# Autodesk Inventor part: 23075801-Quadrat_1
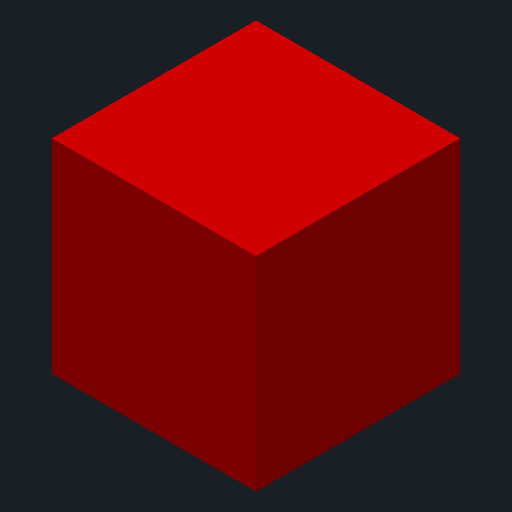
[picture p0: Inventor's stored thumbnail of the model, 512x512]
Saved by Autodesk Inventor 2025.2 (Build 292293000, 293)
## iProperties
Company: Ed. Züblin AG
RuleStatus: InUse
Created: 2025-03
Part Number: 23075801-Quadrat_1
Material: Stahlbeton C30/37
Document SubType Name: Modeling
Designer: FrodlSte
Mass: 2.5e+06 g
Surface Area: 60000 cm^2
Volume: 1e+06 cm^3
Density: 2.5 g/cm^3
Appearance: Beton C30/37
Description: Ausbruch
z_Bereich: Tunnelbau
z_Direktion: Tief- und Tunnelbau
z_Konzerneinheit: Zentrale Technik
z_Matchkey: =<z_Matchkey_010>_<z_Matchkey_020>_<z_Matchkey_030>_<z_Matchkey_040>_<z_Matchkey_050>_<z_Matchkey_060>_<z_Matchkey_070>_<z_Matchkey_080>_<z_Matchkey_090>_<z_Mat
cpiComponentType: Attribut
cpiFitMatchkey: =<z_Matchkey>
z_Matchkey_010: xxxxx
z_Matchkey_020: 5DTUB
z_Matchkey_030: xxx
z_Matchkey_040: xxx
z_Matchkey_050: xxx
z_Matchkey_060: xxx
z_Matchkey_070: xxx
z_Matchkey_080: xxx
z_Matchkey_090: xxx
z_Matchkey_100: xxx
z_Matchkey_110: xxx
z_Matchkey_120: xxxxxxx
z_Matchkey_130: KALO
z_Matchkey_140: xxxx
DocNumber: 23075801-Quadrat_1.ipt
Folder: DL23075801-DE-Pfaffensteigtunnel\BIM\Testmodell
VDS_Category: 09 - BIM - Konstruktion
DBSet_Element:010_Eigentuemer: DBI
DBSet_Element:020_Autor: VP2ZB
DBSet_Element:030_Projektnummer: G.016268527
DBSet_Element:040_Bereich: 01
DBSet_Element:050_Vertragspartner: 02
DBSet_Element:060_Gewerk: 32
DBSet_Element:070_Bauwerk: SB
DBSet_Element:100_Gruppe: Ausbruch
DBSet_Element:110_Element: Ausbruch
DBSet_Element:120_Elementtyp: Strosse
DBSet_Element:130_Identifikationsnummer: ND
DBSet_Element:140_Position_1: KALO
DBSet_Element:150_Position_2: ND
DBSet_Element:160_PUID: ND
DBSet_Element:170_Hauptmaterialitaet: ND
DBSet_Element:171_Materialindikator_1: ND
DBSet_Element:172_Materialindikator_2: ND
DBSet_Geometrie:Flaeche: 1.0
DBSet_Geometrie:Laenge: -99999.0
DBSet_Geometrie:Volumen_Solid: 7.21
DBSet_TP:Status: NBA
DBSet_TU_Ausbruch:Abrechnungsquerschnitt: -99999.0
DBSet_TU_Ausbruch:Abschlagslaenge: 1.0
DBSet_TU_Ausbruch:Modus: ND
DBSet_TU_Ausbruch:Stuetzmittel: ND
DBSet_TU_Ausbruch:ta_cm: 30
DBSet_TU_Ausbruch:tb_cm: 100
DBSet_TU_Ausbruch:td_cm: 300
DBSet_TU_Ausbruch:ti_cm: 300
DBSet_TU_Ausbruch:ue_cm: 400
z_DBSet_Geometrie:Flaeche: 1,000 m^2
z_DBSet_Element:010_Eigentuemer: DBInfraGo
z_DBSet_Element:020_Autor: Vertragspartner 2 ZB
z_DBSet_Element:030_Projektnummer: Gaeubahn Nord HP Goldberg (DBnfraGO, BK11)
z_DBSet_Element:040_Bereich: PFA 1 Tunnel
z_DBSet_Element:050_Vertragspartner: Tunnel
z_DBSet_Element:060_Gewerk: Tunnelbau
z_DBSet_Element:070_Bauwerk: SBW-Tu
z_DBSet_Element:080_Bauwerksnummer: zzz (leer)
z_DBSet_Element:090_Bezeichnung: zzz (leer)
z_DBSet_Element:100_Gruppe: Ausbruch
z_DBSet_Element:110_Element: Ausbruch
z_DBSet_Element:120_Elementtyp: Strosse
z_DBSet_Element:130_Identifikationsnummer: nicht definiert
z_DBSet_Element:140_Position_1: Kalotte
z_DBSet_Element:150_Position_2: Nicht definiert
z_DBSet_Element:160_PUID: nicht definiert
z_DBSet_Element:170_Hauptmaterialitaet: nicht definiert
z_DBSet_Element:171_Materialindikator_1: nicht definiert
z_DBSet_Element:172_Materialindikator_2: nicht definiert
z_DBSet_Geometrie:Laenge: -99999,000 m
z_DBSet_Position:Streckenachse: zzz (leer)
z_DBSet_Position:Streckenkilometer_Anfang: -11111,000 oE
z_DBSet_Position:Streckenkilometer_Ende: -11111,000 oE
z_DBSet_Position:Tunnelachse: zzz (leer)
z_DBSet_Position:Tunnelmeter_Anfang: -11111,000 oE
z_DBSet_Position:Tunnelmeter_Ende: -11111,000 oE
z_DBSet_TP:Status: Neubau
z_DBSet_TU_Ausbruch:Abrasivitaetsindex: zzz (leer)
z_DBSet_TU_Ausbruch:Abrechnungsquerschnitt: -99999,000 m^2
z_DBSet_TU_Ausbruch:Abschlagslaenge: 1,000 m
z_DBSet_TU_Ausbruch:Ausfuehrungsrichtung: zzz (leer)
z_DBSet_TU_Ausbruch:Grenzwassermenge: zzz (leer)
z_DBSet_TU_Ausbruch:Homogenbereich: zzz (leer)
z_DBSet_TU_Ausbruch:Modus: nicht definiert
z_DBSet_TU_Ausbruch:Stuetzmittel: Nicht definiert
z_DBSet_TU_Ausbruch:Vortriebsabschnitt: zzz (leer)
z_DBSet_TU_Ausbruch:Vortriebsklasse: zzz (leer)
z_DBSet_TU_Ausbruch:Wasserzufluss: zzz (leer)
z_DBSet_DDD: DDD
z_DBSet_Geometrie:Volumen_Solid: -11111,000 m^3
z_DBSet_TU_Ausbruch:ta_cm: 30,000 cm
z_DBSet_TU_Ausbruch:tb_cm: 100,000 cm
z_DBSet_TU_Ausbruch:td_cm: 300,000 cm
z_DBSet_TU_Ausbruch:ti_cm: 300,000 cm
z_DBSet_TU_Ausbruch:ue_cm: 400,000 cm
Author: FrodlSte
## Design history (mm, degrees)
derived "23075801-Skelett.ipt"
node "Quadrat_1"
node "Volumenkörpern"
node "Oberflächenkörpern"
feature "Quadrat_1::23075801-Skelett.ipt" dims "d4" = 10
tag "Bezeichnung1"
other parameters: "Ausbruchsfläche_Kalotte_Area" = 100000 [user parameter; used in 1 equation term]
